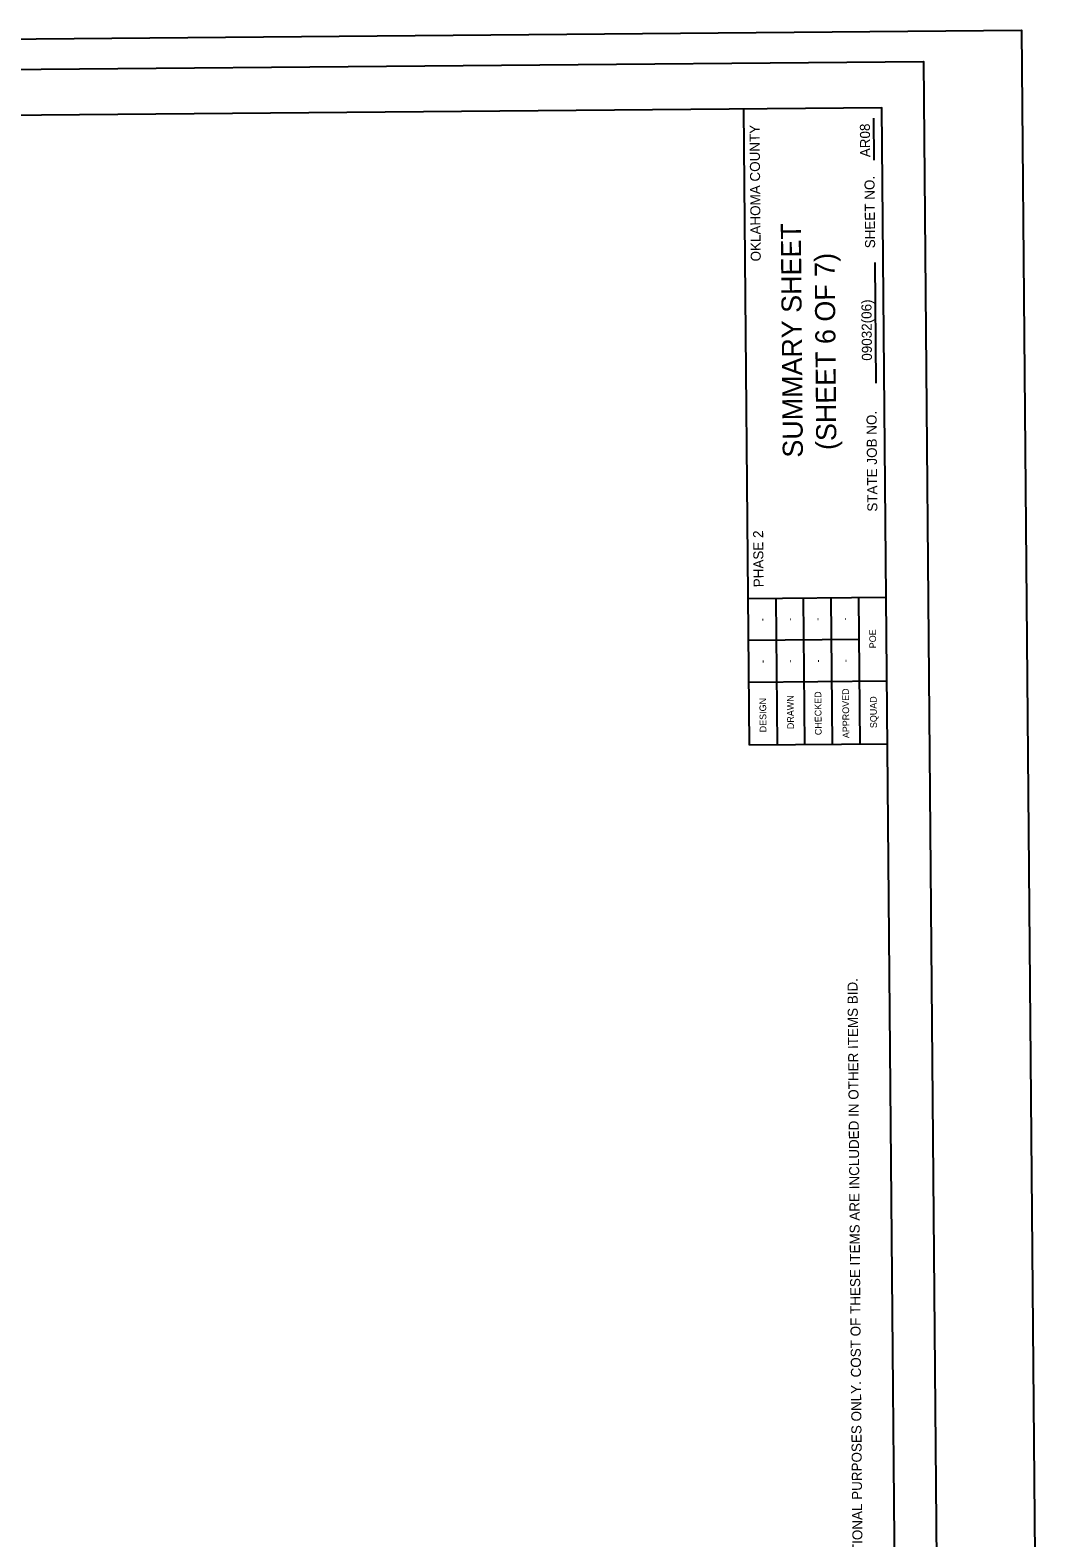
# Model space of a CAD drawing. Extents: x 2151900 to 2151925, y 142567 to 142723.
# Drawn here: x 2151912.23 to 2151924.39, y 142665.4 to 142683.41 of the extents above; entities that cross this region are included whole.
import ezdxf

# ---------------------------------------------------------------- set-up
doc = ezdxf.new("R2010")
doc.units = 0
for name, color, linetype in [('SHT_Plot_Shape_Full', 7, 'Continuous'), ('SHT_Plot_Shape_Half', 7, 'Continuous'), ('SHT_Sheet_Border', 7, 'Continuous'), ('SHT_Standard_Sheet_Lines', 7, 'Continuous'), ('SHT_Standard_Sheet_Txt', 7, 'Continuous'), ('TYP_Typical_Section_Txt', 7, 'Continuous')]:
    doc.layers.add(name, color=color, linetype=linetype)

msp = doc.modelspace()

# ---------------------------------------------------------------- linework, layer by layer
at = {"layer": 'SHT_Plot_Shape_Full'}
msp.add_lwpolyline([(2151900.392, 142647.197), (2151900.077, 142683.196), (2151924.076, 142683.406), (2151924.391, 142647.407)], close=True, dxfattribs=at)
at = {"layer": 'SHT_Plot_Shape_Half'}
msp.add_lwpolyline([(2151901.203, 142648.842), (2151900.905, 142682.841), (2151922.904, 142683.033), (2151923.202, 142649.034)], close=True, dxfattribs=at)
at = {"layer": 'SHT_Sheet_Border'}
for p, q in [((2151920.826, 142674.865), (2151920.759, 142682.464)), ((2151922.46, 142676.629), (2151920.809, 142676.614)), ((2151922.476, 142674.879), (2151920.826, 142674.865))]:
    msp.add_line(p, q, dxfattribs=at)
msp.add_lwpolyline([(2151922.685, 142650.98), (2151922.409, 142682.479), (2151901.41, 142682.295), (2151901.686, 142650.796)], close=True, dxfattribs=at)
at = {"layer": 'SHT_Standard_Sheet_Lines'}
for p, q in [((2151922.318, 142681.853), (2151922.314, 142682.356)), ((2151922.342, 142679.189), (2151922.329, 142680.629)), ((2151922.134, 142676.126), (2151920.814, 142676.114)), ((2151922.469, 142675.629), (2151920.818, 142675.614))]:
    msp.add_line(p, q, dxfattribs=at)
for points in [[(2151921.14, 142676.617), (2151921.156, 142674.867)], [(2151921.47, 142676.62), (2151921.486, 142674.87)], [(2151921.8, 142676.623), (2151921.816, 142674.873)], [(2151922.13, 142676.626), (2151922.146, 142674.876)]]:
    msp.add_lwpolyline(points, dxfattribs=at)

# ---------------------------------------------------------------- texts
at = {"layer": 'SHT_Standard_Sheet_Txt'}
for s, height, p in [('OKLAHOMA COUNTY', 0.12, (2151920.962, 142680.644)), ('AR08', 0.12, (2151922.269, 142681.889)), ('SHEET NO. ', 0.12, (2151922.328, 142680.801)), ('SUMMARY SHEET', 0.24, (2151921.465, 142678.301)), ('(SHEET 6 OF 7)', 0.24, (2151921.865, 142678.392)), ('09032(06)', 0.12, (2151922.29, 142679.458)), ('STATE JOB NO.', 0.12, (2151922.355, 142677.655)), ('PHASE 2', 0.12, (2151920.996, 142676.752)), ('-', 0.08, (2151921.017, 142676.347)), ('-', 0.08, (2151921.347, 142676.35)), ('-', 0.08, (2151921.677, 142676.353)), ('-', 0.08, (2151922.007, 142676.355)), ('POE', 0.08, (2151922.34, 142676.023)), ('-', 0.08, (2151921.021, 142675.847)), ('-', 0.08, (2151921.351, 142675.85)), ('-', 0.08, (2151921.682, 142675.853)), ('-', 0.08, (2151922.012, 142675.855)), ('APPROVED', 0.08, (2151922.02, 142674.949)), ('DESIGN', 0.08, (2151921.029, 142675.019)), ('DRAWN', 0.08, (2151921.358, 142675.057)), ('CHECKED', 0.08, (2151921.689, 142674.985)), ('SQUAD', 0.08, (2151922.349, 142675.069))]:
    msp.add_text(s, height=height, rotation=90.5015, dxfattribs=at).set_placement(p)
at = {"layer": 'TYP_Typical_Section_Txt'}
msp.add_text('(1) QUANTITIES SHOWN ARE FOR INFORMATIONAL PURPOSES ONLY. COST OF THESE ITEMS ARE INCLUDED IN OTHER ITEMS BID.', height=0.12, rotation=90.5015, dxfattribs=at).set_placement((2151922.207, 142661.822))

doc.saveas('drawing.dxf')
